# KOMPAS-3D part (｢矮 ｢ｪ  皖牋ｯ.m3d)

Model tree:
1. Эскиз:1
2. Операция выдавливания:1
     Расстояние 1 = 2
3. Эскиз:2
4. Операция выдавливания:2
     Расстояние 1 = 30
5. Оболочка:1
     Толщина стенки 2 = 2
6. Эскиз:3
7. Операция выдавливания:3
     Расстояние 1 = 30
8. Фаска:1
     Угол = 68; Длина 1 = 12; Длина 2 = 29.701
9. Эскиз:4
10. Операция выдавливания:4
     Расстояние 1 = 7.5; Расстояние 2 = 27.5
11. Скругление:1
     Радиус = 1
12. Скругление:2
     Радиус = 1
13. Скругление:3
     Радиус = 1
14. Скругление:4
     Радиус = 1
15. Скругление:5
     Радиус = 1
16. Скругление:6
     Радиус = 1
17. Эскиз:5
18. Вырезать элемент выдавливания:1
     Расстояние 2 = 19.5; Расстояние 1 = 3
19. Скругление:7
     Радиус = 1
20. Скругление:8
     Радиус = 1
